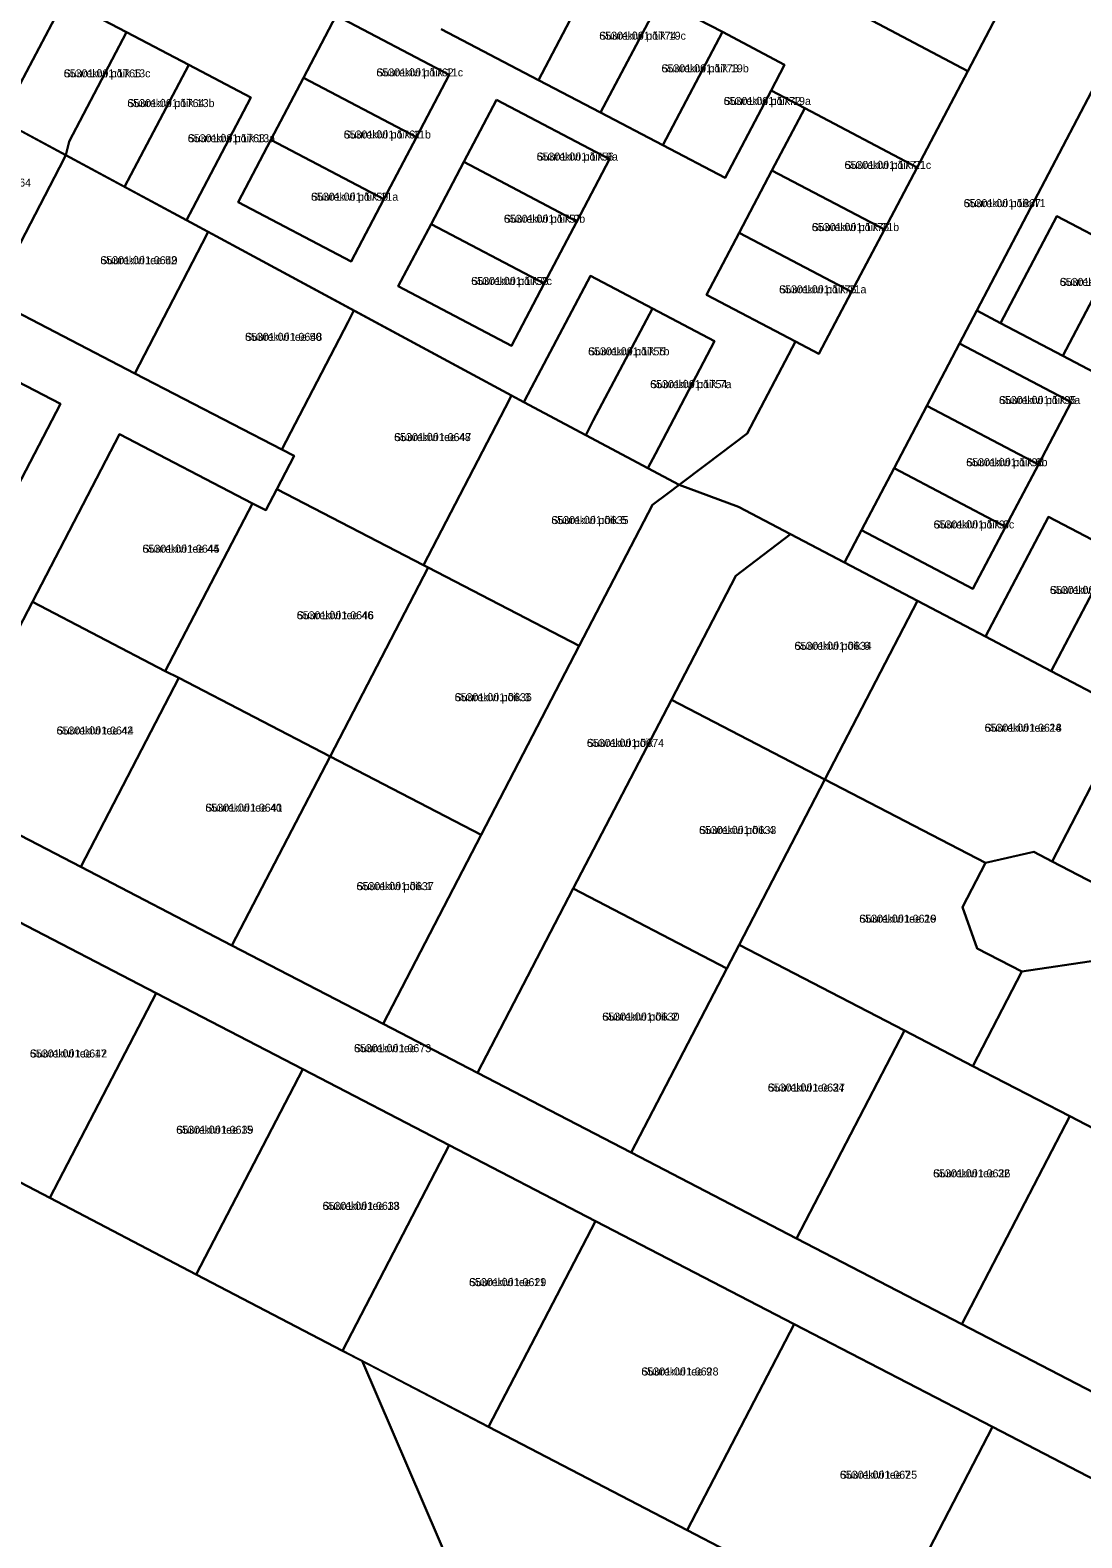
# Model space of a CAD drawing. Extents: x 543236 to 563717, y 6566033 to 6588992.
# Drawn here: x 545592.2 to 545789.8, y 6584755.7 to 6585039 of the extents above; entities that cross this region are included whole.
import ezdxf

# ---------------------------------------------------------------- set-up
doc = ezdxf.new("R2010")
doc.units = 0
for name, color, linetype in [('L_AADRESS', 7, 'Continuous'), ('PIIR', 7, 'Continuous'), ('TUNNUS', 7, 'Continuous')]:
    doc.layers.add(name, color=color, linetype=linetype)

msp = doc.modelspace()

# ---------------------------------------------------------------- linework, layer by layer
at = {"layer": 'PIIR'}
for points in [[(545796.96, 6585037.66), (545770.02, 6584986.31), (545766.77, 6584980.11), (545760.64, 6584968.42), (545754.51, 6584956.73), (545748.38, 6584945.04), (545745.2, 6584938.99), (545735.06, 6584944.32), (545725.29, 6584949.46), (545714.15, 6584953.57), (545719.21, 6584957.4), (545726.9, 6584963.24), (545735.97, 6584980.49), (545740.39, 6584978.17), (545746.53, 6584989.85), (545752.67, 6585001.54), (545758.81, 6585013.22), (545768.34, 6585031.33), (545774.48, 6585043.02), (545780.63, 6585054.7), (545786.77, 6585066.38), (545793.06, 6585078.35)], [(545698.87, 6585050.92), (545687.69, 6585029.64), (545669.41, 6585039.22)], [(545669.41, 6585039.22), (545687.69, 6585029.64), (545699.37, 6585023.51), (545711.06, 6585017.38), (545722.75, 6585011.24), (545731.38, 6585027.65), (545737.71, 6585024.32), (545731.56, 6585012.64), (545725.42, 6585000.95), (545719.28, 6584989.27), (545735.97, 6584980.49), (545726.9, 6584963.24), (545719.21, 6584957.4), (545714.15, 6584953.57), (545708.25, 6584956.71), (545709.67, 6584959.41), (545720.79, 6584980.56), (545709.09, 6584986.72), (545697.45, 6584992.84), (545686.37, 6584971.83), (545684.96, 6584969.13), (545621.57, 6585003.29), (545622.77, 6585005.56), (545633.69, 6585026.34), (545622.01, 6585032.48), (545610.33, 6585038.63), (545598.65, 6585044.77), (545587.93, 6585024.39)], [(545747.1, 6585042.51), (545768.34, 6585031.33), (545758.81, 6585013.22), (545737.71, 6585024.32), (545731.38, 6585027.65), (545733.92, 6585032.49), (545722.25, 6585038.66), (545710.56, 6585044.78)], [(545796.76, 6584997.94), (545785.08, 6585004.08), (545774.49, 6584983.96), (545770.02, 6584986.31), (545796.96, 6585037.66)], [(545584.89, 6584988.52), (545611.88, 6584974.52), (545639.48, 6584960.19), (545641.79, 6584958.99), (545638.56, 6584952.78), (545636.49, 6584948.79), (545634, 6584950.08), (545608.97, 6584963.07), (545592.62, 6584931.56), (545574.2, 6584896.05), (545601.71, 6584881.77), (545630.11, 6584867.03), (545658.52, 6584852.29), (545676.27, 6584843.08), (545705.11, 6584828.11), (545736.18, 6584811.99), (545767.25, 6584795.86), (545792.1, 6584782.96)], [(545810.27, 6584757.2), (545772.99, 6584776.54), (545735.71, 6584795.89), (545698.44, 6584815.24), (545670.92, 6584829.52), (545643.41, 6584843.8), (545615.89, 6584858.08), (545588.37, 6584872.36), (545560.86, 6584886.64), (545558.56, 6584882.2), (545553.23, 6584884.96), (545555.53, 6584889.4), (545533.34, 6584900.92), (545503.96, 6584916.17), (545489.47, 6584875.03), (545471.54, 6584884.32), (545475.8, 6584896.41), (545484.9, 6584922.24), (545471.28, 6584947.73), (545457.12, 6584974.22), (545427.3, 6584956.26), (545423.21, 6584962.28)], [(545792.82, 6584864.27), (545778.52, 6584862.12), (545770.13, 6584866.47), (545767.34, 6584874.2), (545771.68, 6584882.57), (545780.78, 6584884.6), (545784.21, 6584882.82), (545831.75, 6584858.15)]]:
    msp.add_lwpolyline(points, dxfattribs=at)
for points in [[(545753.24, 6585054.19), (545774.48, 6585043.02), (545768.34, 6585031.33), (545747.1, 6585042.51)], [(545698.87, 6585050.92), (545710.56, 6585044.78), (545699.37, 6585023.51), (545687.69, 6585029.64)], [(545598.65, 6585044.77), (545610.33, 6585038.63), (545599.54, 6585018.11), (545598.92, 6585015.53), (545586.73, 6585022.12), (545587.93, 6585024.39)], [(545710.56, 6585044.78), (545722.25, 6585038.66), (545711.06, 6585017.38), (545699.37, 6585023.51)], [(545649.71, 6585041.75), (545643.56, 6585030.07), (545637.42, 6585018.39), (545631.28, 6585006.7), (545652.52, 6584995.53), (545658.66, 6585007.22), (545664.8, 6585018.9), (545670.95, 6585030.58)], [(545649.71, 6585041.75), (545670.95, 6585030.58), (545664.8, 6585018.9), (545643.56, 6585030.07)], [(545610.33, 6585038.63), (545622.01, 6585032.48), (545611.15, 6585011.84), (545609.96, 6585009.57), (545598.92, 6585015.53), (545599.54, 6585018.11)], [(545722.25, 6585038.66), (545733.92, 6585032.49), (545731.38, 6585027.65), (545722.75, 6585011.24), (545711.06, 6585017.38)], [(545570.85, 6585030.7), (545598.92, 6585015.53), (545597.72, 6585013.22), (545584.89, 6584988.52), (545556.58, 6585003.22), (545569.63, 6585028.37)], [(545622.01, 6585032.48), (545633.69, 6585026.34), (545622.77, 6585005.56), (545621.57, 6585003.29), (545609.96, 6585009.57), (545611.15, 6585011.84)], [(545643.56, 6585030.07), (545664.8, 6585018.9), (545658.66, 6585007.22), (545637.42, 6585018.39)], [(545679.8, 6585025.93), (545673.65, 6585014.24), (545667.51, 6585002.56), (545661.37, 6584990.88), (545682.61, 6584979.71), (545688.75, 6584991.39), (545694.9, 6585003.07), (545701.04, 6585014.76)], [(545679.8, 6585025.93), (545701.04, 6585014.76), (545694.9, 6585003.07), (545673.65, 6585014.24)], [(545737.71, 6585024.32), (545758.81, 6585013.22), (545752.67, 6585001.54), (545731.56, 6585012.64)], [(545637.42, 6585018.39), (545658.66, 6585007.22), (545652.52, 6584995.53), (545631.28, 6585006.7)], [(545598.92, 6585015.53), (545625.66, 6585001.08), (545624.52, 6584998.89), (545611.88, 6584974.52), (545584.89, 6584988.52), (545597.72, 6585013.22)], [(545673.65, 6585014.24), (545694.9, 6585003.07), (545688.75, 6584991.39), (545667.51, 6585002.56)], [(545731.56, 6585012.64), (545752.67, 6585001.54), (545746.53, 6584989.85), (545725.42, 6585000.95)], [(545470.88, 6584979.41), (545483.58, 6584955.54), (545492.74, 6584938.33), (545509.85, 6584929.45), (545535.59, 6584916.09), (545557.78, 6584904.58), (545563.1, 6584901.81), (545565.4, 6584906.25), (545581.53, 6584937.32), (545597.88, 6584968.82), (545570.36, 6584983.1), (545544.63, 6584996.46), (545520.42, 6585009.02), (545505.27, 6584999.96)], [(545667.51, 6585002.56), (545688.75, 6584991.39), (545682.61, 6584979.71), (545661.37, 6584990.88)], [(545785.08, 6585004.08), (545796.76, 6584997.94), (545786.18, 6584977.81), (545774.49, 6584983.96)], [(545625.66, 6585001.08), (545653.03, 6584986.3), (545651.93, 6584984.19), (545639.48, 6584960.19), (545611.88, 6584974.52), (545624.52, 6584998.89)], [(545725.42, 6585000.95), (545746.53, 6584989.85), (545740.39, 6584978.17), (545735.97, 6584980.49), (545719.28, 6584989.27)], [(545796.76, 6584997.94), (545808.44, 6584991.8), (545797.86, 6584971.67), (545786.18, 6584977.81)], [(545697.45, 6584992.84), (545709.09, 6584986.72), (545698, 6584965.63), (545696.58, 6584962.93), (545684.96, 6584969.13), (545686.37, 6584971.83)], [(545653.03, 6584986.3), (545682.62, 6584970.38), (545681.42, 6584968.06), (545666.08, 6584938.5), (545638.56, 6584952.78), (545641.79, 6584958.99), (545639.48, 6584960.19), (545651.93, 6584984.19)], [(545709.09, 6584986.72), (545720.79, 6584980.56), (545709.67, 6584959.41), (545708.25, 6584956.71), (545696.58, 6584962.93), (545698, 6584965.63)], [(545770.02, 6584986.31), (545774.49, 6584983.96), (545786.18, 6584977.81), (545797.86, 6584971.67), (545809.54, 6584965.52), (545812.16, 6584970.38), (545818.3, 6584967.15), (545812.3, 6584955.61), (545806.16, 6584943.93), (545822.62, 6584935.28), (545819.22, 6584928.8), (545807.53, 6584934.94), (545795.85, 6584941.09), (545783.53, 6584947.57), (545771.69, 6584925.06), (545758.92, 6584931.78), (545745.2, 6584938.99), (545748.38, 6584945.04), (545769.32, 6584934.03), (545775.46, 6584945.71), (545781.6, 6584957.4), (545787.75, 6584969.08), (545766.77, 6584980.11)], [(545570.36, 6584983.1), (545597.88, 6584968.82), (545581.53, 6584937.32), (545554.01, 6584951.6)], [(545766.77, 6584980.11), (545787.75, 6584969.08), (545781.6, 6584957.4), (545760.64, 6584968.42)], [(545682.62, 6584970.38), (545684.96, 6584969.13), (545696.58, 6584962.93), (545708.25, 6584956.71), (545714.15, 6584953.57), (545712.04, 6584951.98), (545709.12, 6584949.8), (545695.37, 6584923.3), (545666.97, 6584938.04), (545666.08, 6584938.5), (545681.42, 6584968.06)], [(545760.64, 6584968.42), (545781.6, 6584957.4), (545775.46, 6584945.71), (545754.51, 6584956.73)], [(545608.97, 6584963.07), (545634, 6584950.08), (545617.6, 6584918.59), (545592.62, 6584931.56)], [(545754.51, 6584956.73), (545775.46, 6584945.71), (545769.32, 6584934.03), (545748.38, 6584945.04)], [(545634, 6584950.08), (545636.49, 6584948.79), (545638.56, 6584952.78), (545666.08, 6584938.5), (545666.97, 6584938.04), (545648.54, 6584902.54), (545620.14, 6584917.28), (545617.6, 6584918.59)], [(545714.15, 6584953.57), (545725.29, 6584949.46), (545735.06, 6584944.32), (545724.75, 6584936.5), (545712.66, 6584913.2), (545694.23, 6584877.7), (545676.27, 6584843.08), (545658.52, 6584852.29), (545676.94, 6584887.8), (545695.37, 6584923.3), (545709.12, 6584949.8), (545712.04, 6584951.98)], [(545783.53, 6584947.57), (545795.85, 6584941.09), (545784.01, 6584918.58), (545771.69, 6584925.06)], [(545724.75, 6584936.5), (545735.06, 6584944.32), (545758.92, 6584931.78), (545741.51, 6584898.23), (545712.66, 6584913.2)], [(545795.85, 6584941.09), (545807.53, 6584934.94), (545795.7, 6584912.44), (545784.01, 6584918.58)], [(545666.97, 6584938.04), (545695.37, 6584923.3), (545676.94, 6584887.8), (545648.54, 6584902.54)], [(545592.62, 6584931.56), (545617.6, 6584918.59), (545620.14, 6584917.28), (545601.71, 6584881.77), (545574.2, 6584896.05)], [(545758.92, 6584931.78), (545771.69, 6584925.06), (545784.01, 6584918.58), (545795.7, 6584912.44), (545798.75, 6584910.83), (545784.21, 6584882.82), (545780.78, 6584884.6), (545771.68, 6584882.57), (545741.51, 6584898.23)], [(545620.14, 6584917.28), (545648.54, 6584902.54), (545630.11, 6584867.03), (545601.71, 6584881.77)], [(545712.66, 6584913.2), (545741.51, 6584898.23), (545725.38, 6584867.16), (545723.08, 6584862.72), (545694.23, 6584877.7)], [(545798.75, 6584910.83), (545807.36, 6584906.26), (545824.95, 6584897.05), (545836.63, 6584890.91), (545846.1, 6584885.93), (545831.75, 6584858.15), (545784.21, 6584882.82)], [(545648.54, 6584902.54), (545676.94, 6584887.8), (545658.52, 6584852.29), (545630.11, 6584867.03)], [(545741.51, 6584898.23), (545771.68, 6584882.57), (545767.34, 6584874.2), (545770.13, 6584866.47), (545778.52, 6584862.12), (545769.3, 6584844.37), (545756.45, 6584851.04), (545725.38, 6584867.16)], [(545694.23, 6584877.7), (545723.08, 6584862.72), (545705.11, 6584828.11), (545676.27, 6584843.08)], [(545588.37, 6584872.36), (545615.89, 6584858.08), (545595.9, 6584819.6), (545568.44, 6584833.94)], [(545725.38, 6584867.16), (545756.45, 6584851.04), (545736.18, 6584811.99), (545705.11, 6584828.11), (545723.08, 6584862.72)], [(545778.52, 6584862.12), (545792.82, 6584864.27), (545830.82, 6584844.55), (545817.69, 6584819.25), (545787.51, 6584834.92), (545769.3, 6584844.37)], [(545522.71, 6584801.88), (545515.72, 6584861.42), (545540.95, 6584848.28), (545568.44, 6584833.94), (545595.9, 6584819.6), (545623.37, 6584805.21), (545650.89, 6584790.87), (545654.59, 6584788.95), (545726.79, 6584620.99), (545552.43, 6584545.79), (545548.01, 6584583.61), (545542.31, 6584632.89), (545539.87, 6584653.16), (545534.53, 6584699.52), (545531.48, 6584725.86), (545531.11, 6584728.87), (545530.7, 6584731.91)], [(545615.89, 6584858.08), (545643.41, 6584843.8), (545623.37, 6584805.21), (545595.9, 6584819.6)], [(545756.45, 6584851.04), (545769.3, 6584844.37), (545787.51, 6584834.92), (545767.25, 6584795.86), (545736.18, 6584811.99)], [(545643.41, 6584843.8), (545670.92, 6584829.52), (545650.89, 6584790.87), (545623.37, 6584805.21)], [(545787.51, 6584834.92), (545817.69, 6584819.25), (545799.73, 6584784.64), (545794.4, 6584787.4), (545792.1, 6584782.96), (545767.25, 6584795.86)], [(545670.92, 6584829.52), (545698.44, 6584815.24), (545678.32, 6584776.54), (545650.89, 6584790.87)], [(545698.44, 6584815.24), (545735.71, 6584795.89), (545715.64, 6584757.18), (545678.32, 6584776.54)], [(545735.71, 6584795.89), (545772.99, 6584776.54), (545752.91, 6584737.72), (545715.64, 6584757.18)], [(545726.79, 6584620.99), (545654.59, 6584788.95), (545678.32, 6584776.54), (545715.64, 6584757.18), (545752.91, 6584737.72), (545790.07, 6584718.33), (545827.29, 6584698.94), (545872.72, 6584675.22), (545839.95, 6584669.53)], [(545772.99, 6584776.54), (545810.27, 6584757.2), (545790.07, 6584718.33), (545752.91, 6584737.72)]]:
    msp.add_lwpolyline(points, close=True, dxfattribs=at)

# ---------------------------------------------------------------- texts
at = {"layer": 'L_AADRESS'}
for s, p in [('Suurekivi põik 19c', (545699.12, 6585037.21)), ('Suurekivi põik 13c', (545598.53, 6585030.14)), ('Suurekivi põik 11c', (545657.26, 6585030.32)), ('Suurekivi põik 19b', (545710.81, 6585031.08)), ('Suurekivi põik 13b', (545610.46, 6585024.55)), ('Suurekivi põik 19a', (545722.49, 6585024.95)), ('Suurekivi põik 13a', (545621.82, 6585017.95)), ('Suurekivi põik 11b', (545651.11, 6585018.65)), ('Suurekivi põik 9a', (545687.35, 6585014.5)), ('Suurekivi põik 21c', (545745.19, 6585012.93)), ('Suurekivi põik 11a', (545644.97, 6585006.96)), ('Suurekivi põik T1', (545767.57, 6585005.75)), ('Suurekivi põik 9b', (545681.2, 6585002.82)), ('Suurekivi põik 21b', (545739.05, 6585001.25)), ('Suurekivi tee 52', (545605.39, 6584995.03)), ('Suurekivi põik 9c', (545675.06, 6584991.13)), ('Suurekivi põik 21a', (545732.91, 6584989.56)), ('Suurekivi põik 14a', (545785.62, 6584990.95)), ('Suurekivi tee 50', (545632.57, 6584980.63)), ('Suurekivi põik 7b', (545697.03, 6584977.91)), ('Suurekivi põik 7a', (545708.68, 6584971.74)), ('Suurekivi põik 8a', (545774.2, 6584968.75)), ('Suurekivi tee 48', (545660.59, 6584961.79)), ('Suurekivi põik 8b', (545768.05, 6584957.07)), ('Suurekivi põik 5', (545690.11, 6584946.2)), ('Suurekivi põik 8c', (545761.92, 6584945.38)), ('Suurekivi tee 44', (545613.31, 6584940.82)), ('Suurekivi põik 10a', (545783.77, 6584933.07)), ('Suurekivi tee 46', (545642.29, 6584928.32)), ('Suurekivi põik 6', (545735.79, 6584922.57)), ('Suurekivi põik 3', (545671.95, 6584912.92)), ('Suurekivi tee 42', (545597.17, 6584906.66)), ('Suurekivi tee 24', (545771.5, 6584907.18)), ('Suurekivi põik', (545696.79, 6584904.33)), ('Suurekivi tee 40', (545625.12, 6584892.16)), ('Suurekivi põik 4', (545717.87, 6584887.96)), ('Suurekivi põik 1', (545653.52, 6584877.42)), ('Suurekivi tee 26', (545747.96, 6584871.3)), ('Suurekivi põik 2', (545699.68, 6584852.9)), ('Suurekivi tee 17', (545592.16, 6584845.97)), ('Suurekivi tee', (545653.04, 6584846.97)), ('Suurekivi tee 34', (545730.78, 6584839.57)), ('Suurekivi tee 15', (545619.65, 6584831.64)), ('Suurekivi tee 32', (545761.84, 6584823.45)), ('Suurekivi tee 13', (545647.14, 6584817.34)), ('Suurekivi tee 11', (545674.66, 6584803.01)), ('Suurekivi tee 9', (545707.02, 6584786.22)), ('Suurekivi tee 7', (545744.32, 6584766.82))]:
    msp.add_text(s, height=1.5, dxfattribs=at).set_placement(p)
at = {"layer": 'TUNNUS'}
for s, p in [('65301:001:1774', (545699.12, 6585037.21)), ('65301:001:1765', (545598.53, 6585030.14)), ('65301:001:1762', (545657.26, 6585030.32)), ('65301:001:1773', (545710.81, 6585031.08)), ('65301:001:1764', (545610.46, 6585024.55)), ('65301:001:1772', (545722.49, 6585024.95)), ('65301:001:1763', (545621.82, 6585017.95)), ('65301:001:1761', (545651.11, 6585018.65)), ('65301:001:1756', (545687.35, 6585014.5)), ('65301:001:1777', (545745.19, 6585012.93)), ('65301:001:0664', (545577.87, 6585009.61)), ('65301:001:1759', (545644.97, 6585006.96)), ('65301:001:1867', (545767.57, 6585005.75)), ('65301:001:1757', (545681.2, 6585002.82)), ('65301:001:1776', (545739.05, 6585001.25)), ('65301:001:0649', (545605.39, 6584995.03)), ('65301:001:1758', (545675.06, 6584991.13)), ('65301:001:1775', (545732.91, 6584989.56)), ('65301:001:1804', (545785.62, 6584990.95)), ('65301:001:0648', (545632.57, 6584980.63)), ('65301:001:1755', (545697.03, 6584977.91)), ('65301:001:1754', (545708.68, 6584971.74)), ('65301:001:1795', (545774.2, 6584968.75)), ('65301:001:0647', (545660.59, 6584961.79)), ('65301:001:1796', (545768.05, 6584957.07)), ('65301:001:0635', (545690.11, 6584946.2)), ('65301:001:1797', (545761.92, 6584945.38)), ('65301:001:0645', (545613.31, 6584940.82)), ('65301:001:1798', (545783.77, 6584933.07)), ('65301:001:0646', (545642.29, 6584928.32)), ('65301:001:0634', (545735.79, 6584922.57)), ('65301:001:0636', (545671.95, 6584912.92)), ('65301:001:0644', (545597.17, 6584906.66)), ('65301:001:0618', (545771.5, 6584907.18)), ('65301:001:0674', (545696.79, 6584904.33)), ('65301:001:0641', (545625.12, 6584892.16)), ('65301:001:0633', (545717.87, 6584887.96)), ('65301:001:0637', (545653.52, 6584877.42)), ('65301:001:0619', (545747.96, 6584871.3)), ('65301:001:0630', (545699.68, 6584852.9)), ('65301:001:0642', (545592.16, 6584845.97)), ('65301:001:0673', (545653.04, 6584846.97)), ('65301:001:0627', (545730.78, 6584839.57)), ('65301:001:0639', (545619.65, 6584831.64)), ('65301:001:0626', (545761.84, 6584823.45)), ('65301:001:0638', (545647.14, 6584817.34)), ('65301:001:0629', (545674.66, 6584803.01)), ('65301:001:0628', (545707.02, 6584786.22)), ('65301:001:0625', (545744.32, 6584766.82))]:
    msp.add_text(s, height=1.5, dxfattribs=at).set_placement(p)

doc.saveas('drawing.dxf')
